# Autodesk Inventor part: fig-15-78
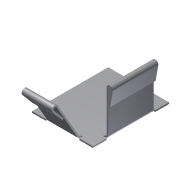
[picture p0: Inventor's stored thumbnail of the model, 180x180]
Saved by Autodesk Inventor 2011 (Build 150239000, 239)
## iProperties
Shininess: 77.0
Angle Display Precision: 2
Document Length Units: 11269
Document Angle Units: 11279
Document Time Units: 11290
Document Mass Units: 11283
Document Length Units Precision: 3
Document Angle Units Precision: 2
Compacted: True
Created: 2002-04
Part Number: fig-15-78
Document SubType Name: Sheet Metal
Density: 1 g/cm^3
Sheet Metal Rule: Default
Density: 0.0
Volumn: 0.0
Area: 0.0
PropertySet Name: Model Information
Control State: 0
Master: False
Checked Out: False
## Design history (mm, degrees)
node "Face1"
  sketch "Sketch1"
    geometry: L1 (-17.882, 11.882)-(2.118, 11.882); L2 (2.118, 11.882)-(2.118, -13.176); L3 (2.118, -13.176)-(-17.882, -13.176); L4 (-17.882, -13.176)-(-17.882, 11.882)
    constraints: 8 end point, 2 parallel, 1 horizontal, 1 perpendicular
    dimensions: "d17" = 20 distance of L2.end L3.end
node "Flange2"
node "Flange3"
feature "Hem8" dims "d82" = 0.5 (= BendReliefWidth), "d83" = 0.25 (= BendReliefDepth), "d84" = 1 (= MinimumRemnant), "d85" = 0.5 (= BendRadius), "d96" = 190 deg, "d97" = 0.5 (= BendRadius), "d98" = 0.5 (= d97), "SeamGap" = 0.01, "Thickness" = 0.5
feature "Hem9" dims "d89" = 0.5 (= BendReliefWidth), "d90" = 0.25 (= BendReliefDepth), "d91" = 1 (= MinimumRemnant), "d92" = 0.5 (= BendRadius), "d99" = 190 deg, "d100" = 0.5 (= BendRadius), "d101" = 0.5 (= d100), "SeamGap" = 0.01, "Thickness" = 0.5
body "Solid1"
face "Plate1" dims "Thickness" = 0.5
sketch "Sketch3"
  geometry: L1 (5, 0)-(20, 0); L2 (20, 0)-(20, 15); L3 (20, 15)-(5, 15); L4 (5, 15)-(5, 0)
  constraints: 8 end point
face "Plate3" dims "d6" = 15, "d7" = 90 deg, "d8" = 0.5 (= BendRadius), "d18" = 5, "d19" = 15, "Thickness" = 0.5, "MinimumRemnant" = 1 (= 2 x Thickness), "BendReliefWidth" = 0.5 (= Thickness)
bend "Bend2" dims "d6" = 15, "d7" = 90 deg, "d8" = 0.5 (= BendRadius), "d56" = 0.5 (= BendReliefWidth), "d57" = 0.25 (= BendReliefDepth), "d58" = 1 (= MinimumRemnant), "SeamGap" = 0.01, "Thickness" = 0.5, "MinimumRemnant" = 1 (= 2 x Thickness), "BendReliefWidth" = 0.5 (= Thickness), "TransitionRadius" = 0.5 (= BendRadius)
sketch "Sketch6"
  geometry: L1 (15, 0)-(5, 0); L2 (5, 0)-(5, 15); L3 (5, 15)-(15, 15); L4 (15, 15)-(15, 0)
  constraints: 8 end point
face "Plate4" dims "d20" = 5, "d21" = 10, "d23" = 15, "d24" = 60 deg, "d25" = 0.5 (= BendRadius), "Thickness" = 0.5, "MinimumRemnant" = 1 (= 2 x Thickness), "BendReliefWidth" = 0.5 (= Thickness)
bend "Bend3" dims "d22" = 0.5 (= BendRadius), "d23" = 15, "d24" = 60 deg, "d25" = 0.5 (= BendRadius), "d59" = 0.5 (= BendReliefWidth), "d60" = 0.25 (= BendReliefDepth), "d61" = 1 (= MinimumRemnant), "SeamGap" = 0.01, "Thickness" = 0.5, "MinimumRemnant" = 1 (= 2 x Thickness), "BendReliefWidth" = 0.5 (= Thickness)
sketch "Sketch12"
  geometry: L1 (0.433, 0.25)-(0, 0); L2 (-0.816, -0.571)-(2.395, -4.398); L3 (2.395, -4.398)-(2.012, -4.719); L4 (2.012, -4.719)-(-1.199, -0.893); A1 r 0.5 centre (-0.433, -0.25) between (0, 0) and (-0.816, -0.571); A2 r 1 centre (-0.433, -0.25) between (0.433, 0.25) and (-1.199, -0.893); 2 further points
  constraints: 8 end point, 4 point on circle
sketch "Sketch13"
  geometry: L1 (0.5, 0)-(0, 0); L2 (-0.992, -0.087)-(-0.125, -5.006); L3 (-0.125, -5.006)-(-0.617, -5.093); L4 (-0.617, -5.093)-(-1.485, -0.174); A1 r 0.5 centre (-0.5, 0) between (0, 0) and (-0.992, -0.087); A2 r 1 centre (-0.5, 0) between (0.5, 0) and (-1.485, -0.174); 2 further points
  constraints: 8 end point, 4 point on circle
other parameters: "BendRadius" = 0.5 (= Thickness), "BendReliefDepth" = 0.25 (= 0.5 x Thickness), "CornerReliefSize" = 2 (= 4 x Thickness), "d0" = 0.5 (= BendRadius), "d5" = 0.5 (= BendRadius), "d26" = 0.5 (= BendRadius), "d30" = 0.5 (= BendRadius), "JacobiRadiusSize" = 0.5 (= Thickness), "GapSize" = 0.5 (= Thickness)
